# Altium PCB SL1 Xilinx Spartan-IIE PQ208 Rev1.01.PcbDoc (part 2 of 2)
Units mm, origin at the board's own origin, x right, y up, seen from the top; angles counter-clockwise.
Board outline 180.01 x 50.51 mm, 2 copper layers (Top Layer, Bottom Layer), stack 1.646 mm thick; 115 components, 126 nets, 642 pads, 225 vias.
Unrouted connection lines stored in the file: 2.
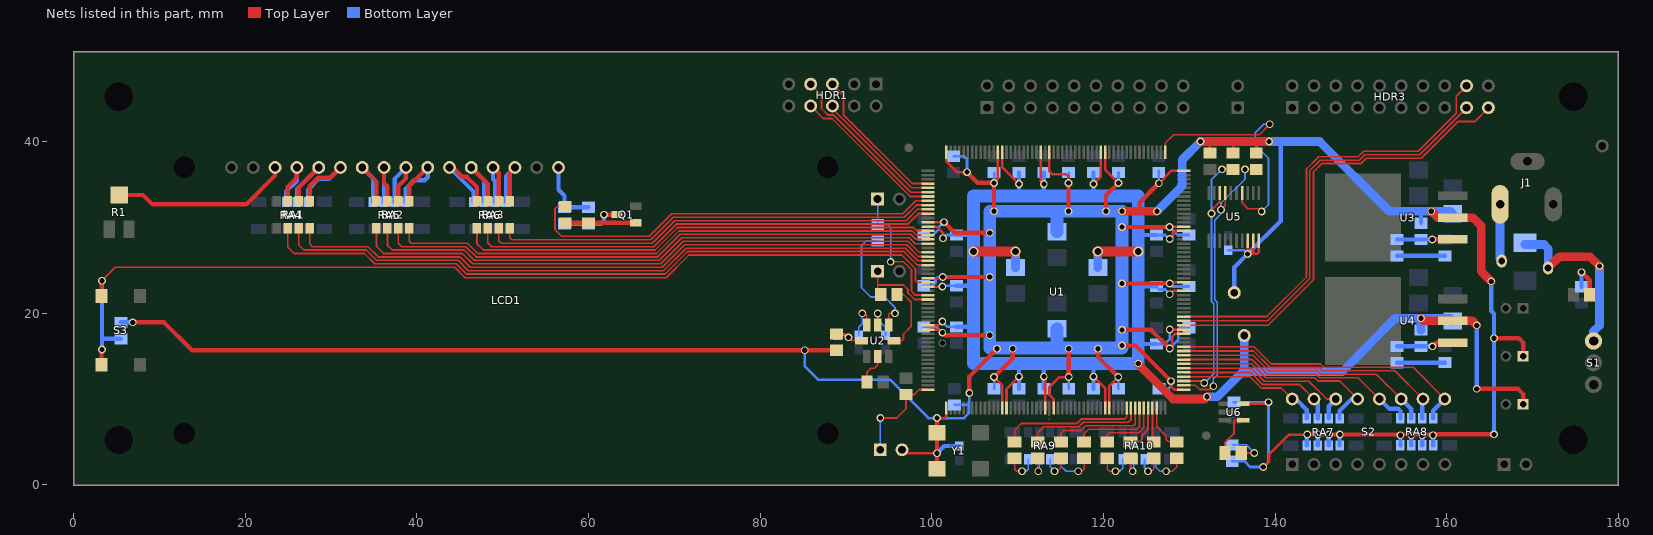
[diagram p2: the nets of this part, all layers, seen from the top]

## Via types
v1: diameter 0.9, hole 0.6, Top Layer to Bottom Layer, tented both sides, 168 vias
v2: diameter 1.5, hole 0.8, Top Layer to Bottom Layer, tented both sides, 27 vias
v3: diameter 1.2, hole 0.8, Top Layer to Bottom Layer, 18 vias
v4: diameter 1.2, hole 0.8, Top Layer to Bottom Layer, tented both sides, 11 vias
v5: diameter 0.9, hole 0.6, Top Layer to Bottom Layer, 1 vias

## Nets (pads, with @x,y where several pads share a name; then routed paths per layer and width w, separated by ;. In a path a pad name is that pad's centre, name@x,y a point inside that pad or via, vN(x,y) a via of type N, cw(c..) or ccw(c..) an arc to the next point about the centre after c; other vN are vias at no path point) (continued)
HB17: HDR3.17 U1.121 | length 50.6
  Top Layer w0.2: U1.121@129.35,19.125 139.109,19.125 144.05,24.066 144.05,36.646 145.254,37.85 149.823,37.85 150.448,38.475 156.835,38.475 HDR3.17@162.32,43.96
HB18: HDR3.18 U1.122 | length 52.6
  Top Layer w0.2: U1.122@129.35,19.625 139.044,19.625 143.65,24.231 143.65,36.812 145.088,38.25 149.657,38.25 150.307,38.9 156.694,38.9 161.1,43.306 161.1,45.28 HDR3.18@162.32,46.5
HB19: HDR3.19 U1.120 | length 53.4
  Top Layer w0.2: U1.120@129.35,18.625 139.175,18.625 144.475,23.925 144.475,36.505 145.42,37.45 149.988,37.45 150.613,38.075 157.025,38.075 161.291,42.341 163.241,42.341 HDR3.19@164.86,43.96
I\N\I\T\: R5.2 U1.107 U5.8 | length 32.6
  Top Layer w0.2: U1.107@129.35,12.125 131.5,12.125 v1(131.75,11.875) ; v1(132.575,31.625) 132.575,32.025 133.55,33 U5.8@133.55,34 ; v1(133.803,36.78) R5.2@135.1,36.775
  Bottom Layer w0.2: v1(131.75,11.875) 132.85,12.975 132.85,21.132 132.575,21.407 132.575,35.552 v1(133.803,36.78)
JTAG_NEXUS_TCK: HDR1.7 U1.6 | length 19.8
  Top Layer w0.2: HDR1.7@85.88,46.7 87.15,45.43 87.15,43.875 87.925,43.1 88.575,43.1 97.55,34.125 U1.6@99.55,34.125
JTAG_NEXUS_TDI: HDR1.5 U1.4 | length 17.3
  Top Layer w0.2: HDR1.5@88.42,46.7 89.7,45.42 89.7,43.15 97.725,35.125 U1.4@99.55,35.125
JTAG_NEXUS_TDO: HDR1.6 U1.5 | length 15.3
  Top Layer w0.2: HDR1.6@88.42,44.16 88.42,43.83 97.625,34.625 U1.5@99.55,34.625
JTAG_NEXUS_TMS: HDR1.8 U1.7 | length 18
  Top Layer w0.2: HDR1.8@85.88,44.16 87.34,42.7 88.375,42.7 97.45,33.625 U1.7@99.55,33.625
LCD_CONTRAST: LCD1.3 R1.W | length 21
  Top Layer w0.5: R1.W@5.3,33.8 8.1,33.8 9.2,32.7 20.113,32.7 23.48,36.067 LCD1.3@23.48,37
LCD_DB0: RA2.5 U1.20 | length 68.8
  Top Layer w0.2: RA2.5@35.295,29.925 35.295,27.8 36.12,26.975 45.3,26.975 46.5,25.775 68.41,25.775 71.035,28.4 97.225,28.4 98.5,27.125 U1.20@99.55,27.125
LCD_DB1: RA2.6 U1.18 | length 67.1
  Top Layer w0.2: RA2.6@36.565,29.925 36.565,27.935 37.125,27.375 45.5,27.375 46.7,26.175 68.244,26.175 70.869,28.8 97.391,28.8 98.066,28.125 U1.18@99.55,28.125
LCD_DB2: RA2.7 U1.17 | length 65.5
  Top Layer w0.2: RA2.7@37.835,29.925 37.835,28.165 38.225,27.775 45.7,27.775 46.9,26.575 68.078,26.575 70.703,29.2 97.556,29.2 98.131,28.625 U1.17@99.55,28.625
LCD_DB3: RA2.8 U1.16 | length 63.8
  Top Layer w0.2: RA2.8@39.105,29.925 39.105,28.395 39.325,28.175 45.9,28.175 47.1,26.975 67.913,26.975 70.538,29.6 97.722,29.6 98.197,29.125 U1.16@99.55,29.125
LCD_DB4: RA3.5 U1.15 | length 55.9
  Top Layer w0.2: RA3.5@46.995,29.925 46.995,28.105 47.725,27.375 67.747,27.375 70.372,30 97.888,30 98.263,29.625 U1.15@99.55,29.625
LCD_DB5: RA3.6 U1.11 | length 54.8
  Top Layer w0.2: RA3.6@48.265,29.925 48.265,28.235 48.725,27.775 67.581,27.775 70.206,30.4 97.197,30.4 98.422,31.625 U1.11@99.55,31.625
LCD_DB6: RA3.7 U1.10 | length 53.2
  Top Layer w0.2: RA3.7@49.535,29.925 49.535,28.465 49.825,28.175 67.416,28.175 70.041,30.8 97,30.8 98.325,32.125 U1.10@99.55,32.125
LCD_DB7: RA3.8 U1.9 | length 51.6
  Top Layer w0.2: RA3.8@50.805,29.925 50.805,28.82 51.05,28.575 67.25,28.575 69.875,31.2 96.8,31.2 98.225,32.625 U1.9@99.55,32.625
LCD_DB#0: LCD1.7 RA2.4 RA5.5 | length 9.2
  Top Layer w0.5: LCD1.7@33.64,37 35.295,35.345 RA2.4@35.295,33.075
  Bottom Layer w0.5: LCD1.7@33.64,37 34.895,35.745 RA5.5@34.895,32.975
LCD_DB#1: LCD1.8 RA2.3 RA5.6 | length 8.1
  Top Layer w0.5: LCD1.8@36.18,37 36.18,35.2 36.565,34.815 RA2.3@36.565,33.075
  Bottom Layer w0.5: RA5.6@36.165,32.975 36.165,36.985 LCD1.8@36.18,37
LCD_DB#2: LCD1.9 RA2.2 RA5.7 | length 8.8
  Top Layer w0.5: RA2.2@37.835,33.075 37.835,34.825 38.72,35.71 LCD1.9@38.72,37
  Bottom Layer w0.5: RA5.7@37.435,32.975 37.435,35.715 LCD1.9@38.72,37
LCD_DB#3: LCD1.10 RA2.1 RA5.8 | length 10.6
  Top Layer w0.5: RA2.1@39.105,33.075 39.105,34.845 LCD1.10@41.26,37
  Bottom Layer w0.5: RA5.8@38.705,32.975 38.705,34.505 39.7,35.5 40.9,35.5 41.26,35.86 LCD1.10@41.26,37
LCD_DB#4: LCD1.11 RA3.4 RA6.5 | length 11
  Top Layer w0.5: LCD1.11@43.8,37 44.2,37 45.297,35.903 45.797,35.903 46.995,34.705 RA3.4@46.995,33.075
  Bottom Layer w0.5: LCD1.11@43.8,37 46.595,34.205 RA6.5@46.595,32.975
LCD_DB#5: LCD1.12 RA3.3 RA6.6 | length 9.4
  Top Layer w0.5: LCD1.12@46.34,37 48.265,35.075 RA3.3@48.265,33.075
  Bottom Layer w0.5: LCD1.12@46.34,37 47.865,35.475 RA6.6@47.865,32.975
LCD_DB#6: LCD1.13 RA3.2 RA6.7 | length 8.3
  Top Layer w0.5: LCD1.13@48.88,37 49.535,36.345 RA3.2@49.535,33.075
  Bottom Layer w0.5: LCD1.13@48.88,37 48.88,35.655 49.135,35.4 RA6.7@49.135,32.975
LCD_DB#7: LCD1.14 RA3.1 RA6.8 | length 8.6
  Top Layer w0.5: RA3.1@50.805,33.075 50.805,36.385 LCD1.14@51.42,37
  Bottom Layer w0.5: RA6.8@50.405,32.975 50.405,35.985 LCD1.14@51.42,37
LCD_E: RA1.8 U1.21 | length 76.7
  Top Layer w0.2: RA1.8@27.505,29.925 27.505,28.095 27.825,27.775 34.3,27.775 35.5,26.575 45,26.575 46.2,25.375 68.575,25.375 71.2,28 97.059,28 98.434,26.625 U1.21@99.55,26.625
LCD_E#: LCD1.6 RA1.1 RA4.8 | length 12.5
  Top Layer w0.5: RA1.1@27.505,33.075 27.505,34.805 28.5,35.8 29.9,35.8 LCD1.6@31.1,37
  Bottom Layer w0.5: RA4.8@27.305,32.975 27.305,34.405 28.595,35.695 29.795,35.695 LCD1.6@31.1,37
LCD_LIGHT: R2.1 U1.8 | length 49.2
  Top Layer w0.2: R2.1@57.3,32.45 56.375,32.45 56.1,32.175 56.1,29.725 56.85,28.975 67.084,28.975 69.709,31.6 96.6,31.6 98.125,33.125 U1.8@99.55,33.125
LCD_RS: RA1.6 U1.23 | length 79.8
  Top Layer w0.2: RA1.6@24.965,29.925 24.965,27.735 25.725,26.975 33.9,26.975 35.1,25.775 44.6,25.775 45.8,24.575 68.907,24.575 71.532,27.2 96.725,27.2 98.3,25.625 U1.23@99.55,25.625
LCD_RS#: LCD1.4 RA1.3 RA4.6 | length 8.9
  Top Layer w0.5: RA1.3@24.965,33.075 24.965,34.79 26.02,35.845 LCD1.4@26.02,37
  Bottom Layer w0.5: RA4.6@24.765,32.975 24.765,34.195 26.02,35.45 LCD1.4@26.02,37
LCD_RW: RA1.7 U1.22 | length 78.2
  Top Layer w0.2: RA1.7@26.235,29.925 26.235,27.965 26.825,27.375 34.1,27.375 35.3,26.175 44.8,26.175 46,24.975 68.741,24.975 71.366,27.6 96.894,27.6 98.369,26.125 U1.22@99.55,26.125
LCD_RW#: LCD1.5 RA1.2 RA4.7 | length 10
  Top Layer w0.5: RA1.2@26.235,33.075 26.235,34.675 LCD1.5@28.56,37
  Bottom Layer w0.5: RA4.7@26.035,32.975 26.035,34.475 LCD1.5@28.56,37
LEDS0: LED0.1 U1.102 | length 5.5
  Top Layer w0.2: U1.102@126.2,8.975 126.2,6.825 127.325,5.7 127.325,5.275 127.575,5.025 LED0.1@128.55,5.025
LEDS1: LED1.1 U1.101 | length 4
  Top Layer w0.2: U1.101@125.7,8.975 125.7,8.875 125.7,5.175 LED1.1@125.85,5.025
LEDS2: LED2.1 U1.100 | length 5.4
  Top Layer w0.2: LED2.1@123.15,5.025 124.175,5.025 124.5,5.35 124.5,5.775 125.2,6.475 U1.100@125.2,8.975
LEDS3: LED3.1 U1.99 | length 7.7
  Top Layer w0.2: LED3.1@120.45,5.025 120.45,5.875 120.675,6.1 124.1,6.1 124.7,6.7 U1.99@124.7,8.975
LEDS4: LED4.1 U1.98 | length 9.9
  Top Layer w0.2: LED4.1@117.75,5.025 117.75,6 118.25,6.5 123.9,6.5 124.2,6.8 U1.98@124.2,8.975
LEDS5: LED5.1 U1.97 | length 12
  Top Layer w0.2: LED5.1@115.05,5.025 115.05,6.05 115.35,6.35 117.35,6.35 117.9,6.9 123.525,6.9 123.7,7.075 U1.97@123.7,8.975
LEDS6: LED6.1 U1.96 | length 13.9
  Top Layer w0.2: LED6.1@112.35,5.025 112.35,6.075 113.05,6.775 117.125,6.775 117.65,7.3 122.9,7.3 123.2,7.6 U1.96@123.2,8.975
LEDS7: LED7.1 U1.95 | length 16.1
  Top Layer w0.2: LED7.1@109.65,5.025 109.65,6.375 110.45,7.175 116.959,7.175 117.484,7.7 122.475,7.7 122.7,7.925 U1.95@122.7,8.975
M0: JP5.1 R7.2 U1.52 | length 11.6
  Top Layer w0.2: v1(94,7.8) 95.9,7.8 96.989,8.889 96.989,10.555 97.98,10.555 98.55,11.125 U1.52@99.55,11.125
  Bottom Layer w0.2: JP5.1@94,4.1 v1(94,7.8)
NetC15_1: C15.1 R11.2 U2.8 | length 4.6
  Top Layer w0.2: R11.2@88.88,17.6 89.9,17.6 90.7,16.8 U2.8@91.8,16.8
  Bottom Layer w0.2: C15.1@89,17.45 89.78,17.45 v1(90.3,17.2)
NetC16_1: C16.1 U2.6 | length 4.2
  Top Layer w0.2: U2.6@93.697,18.663 93.702,18.668 v1(93.702,19.988)
  Bottom Layer w0.2: v1(93.702,19.988) 93.702,19.28 94.6,18.383 C16.1@94.6,17.45
NetC19_1: C19.1 U2.7 | length 4.5
  Top Layer w0.2: v1(91.9,20) 92.2,20 92.43,19.77 U2.7@92.43,18.65
  Bottom Layer w0.2: C19.1@91.5,17.45 91.5,18.392 91.9,18.792 v1(91.9,20)
NetD1_2: D1.2 F1.2 S1.3 | length 21.2
  Top Layer w1: F1.2@171.8,25.3 173.1,26.6 176.7,26.6 v1(177.8,25.5)
  Bottom Layer w1: D1.2@169.1,28.022 171.325,28.025 171.8,27.55 F1.2@171.8,25.3 ; S1.3@177.1,16.78 177.1,17.9 177.8,18.58 v1(177.8,25.5)
NetLCD1_16: LCD1.16 R8.1 R9.1 | length 7.7
  Bottom Layer w0.5: LCD1.16@56.5,37 56.5,34.4 57.2,33.7 57.2,32.35 R9.1@60,32.35
NetLED0_2: LED0.2 RA10.5 | length 5.5
  Top Layer w0.2: v1(127.3,1.6) 128.05,1.6 128.55,2.1 LED0.2@128.55,3.125
  Bottom Layer w0.2: RA10.5@126.055,3 126.055,2.125 126.58,1.6 ; 126.58,1.6 v1(127.3,1.6) 126.58,1.6
NetLED1_2: LED1.2 RA10.6 | length 3.6
  Top Layer w0.2: v1(125.2,1.6) 125.6,1.6 125.85,1.85 LED1.2@125.85,3.125
  Bottom Layer w0.2: RA10.6@124.785,3 124.785,2.015 v1(125.2,1.6)
NetLED2_2: LED2.2 RA10.7 | length 3.1
  Top Layer w0.2: LED2.2@123.15,3.125 123.15,1.85 v1(123.4,1.6)
  Bottom Layer w0.2: v1(123.4,1.6) 123.515,1.715 RA10.7@123.515,3
NetLED3_2: LED3.2 RA10.8 | length 4.4
  Top Layer w0.2: LED3.2@120.45,3.125 120.45,1.85 120.7,1.6 v1(121.4,1.6)
  Bottom Layer w0.2: v1(121.4,1.6) 121.9,1.6 122.245,1.945 RA10.8@122.245,3
NetLED4_2: LED4.2 RA9.5 | length 5.1
  Top Layer w0.2: v1(117.055,1.6) 117.45,1.6 117.75,1.9 LED4.2@117.75,3.125
  Bottom Layer w0.2: RA9.5@115.055,3 115.055,2.2 115.655,1.6 v1(117.055,1.6)
NetLED5_2: LED5.2 RA9.6 | length 3.6
  Top Layer w0.2: v1(114.3,1.6) 114.6,1.6 115.05,2.05 LED5.2@115.05,3.125
  Bottom Layer w0.2: RA9.6@113.785,3 113.785,2.115 v1(114.3,1.6)
NetLED6_2: LED6.2 RA9.7 | length 3
  Top Layer w0.2: LED6.2@112.35,3.125 112.35,1.65 v1(112.4,1.6)
  Bottom Layer w0.2: v1(112.4,1.6) 112.515,1.715 RA9.7@112.515,3
NetLED7_2: LED7.2 RA9.8 | length 4.2
  Top Layer w0.2: LED7.2@109.65,3.125 109.65,1.85 109.9,1.6 v1(110.5,1.6)
  Bottom Layer w0.2: v1(110.5,1.6) 111,1.6 111.245,1.845 RA9.8@111.245,3
NetLED8_1: LED8.1 R20.1 | length 4.5
  Top Layer w0.2: LED8.1@136.05,3.725 v1(137.575,3.725)
  Bottom Layer w0.2: R20.1@135,4.675 136.625,4.675 v1(137.575,3.725)
NetLED8_2: LED8.2 U6.4 | length 5.2
  Top Layer w0.2: LED8.2@134.15,3.725 134.15,4.925 135.2,5.975 135.2,7.4 135.35,7.55 U6.4@136.275,7.55
NetLED9_1: LED9.1 R15.1 | length 4.7
  Top Layer w0.5: v1(175.7,24.8) 176.65,23.85 LED9.1@176.65,22.15
  Bottom Layer w0.5: R15.1@175.7,23.1 v1(175.7,24.8)
NetQ1_1: Q1.1 R2.2 R3.2 | length 8.2
  Top Layer w0.5: R2.2@57.3,30.55 Q1.1@65.5,30.55
NetQ1_3: Q1.3 R8.2 R9.2 | length 6.9
  Top Layer w0.5: v1(61.8,31.5) Q1.3@63.3,31.5
  Bottom Layer w0.5: R8.2@57.2,30.45 61.45,30.45 61.8,30.8 v1(61.8,31.5)
NetR10_2: R10.2 U2.2 | length 3.7
  Top Layer w0.2: R10.2@92.45,12 92.45,13.15 92.9,13.6 93.28,13.6 93.7,14.02 U2.2@93.7,14.95
NetR12_1: R12.1 R13.2 U3.1 | length 6.5
  Top Layer w0.5: v1@158.32,28.62 U3.1@160.7,28.62
  Bottom Layer w0.5: R12.1@154.2,28.6 157,28.6 v1(158.3,28.6)
NetR12_2: R12.2 R14.2 | length 5.6
  Bottom Layer w0.5: R12.2@154.2,26.7 R14.2@159.8,26.7
NetR17_1: R17.1 R18.2 U4.1 | length 6.7
  Top Layer w0.5: v1(158.35,16.15) 158.8,16.6 U4.1@160.7,16.6
  Bottom Layer w0.5: R17.1@154.2,16.15 v1(158.35,16.15)
NetR17_2: R17.2 R19.1 | length 5.6
  Bottom Layer w0.5: R17.2@154.2,14.25 R19.1@159.8,14.25
PROG_B: R6.2 U1.106 U5.7 | length 34.3
  Top Layer w0.2: U1.106@129.35,11.625 130.725,11.625 131.225,11.125 132.425,11.125 v1(132.8,11.5) ; v1(133.7,32.075) 134.2,32.575 U5.7@134.2,34 ; v1(136.5,36.775) R6.2@137.8,36.775
  Bottom Layer w0.2: v1(132.8,11.5) 132.8,12.359 133.25,12.809 133.25,21.297 132.975,21.572 132.975,30.867 133.7,31.592 133.7,32.85 136.5,35.65 v1(136.5,36.775)
PWR_IN: F1.1 J1.1 | length 7.9
  Bottom Layer w1: J1.1@166.2,33.95 166.2,26.35 F1.1@166.4,26.1
SW0: RA7.1 S2.16 U1.108 | length 17.8
  Top Layer w0.2: U1.108@129.35,12.625 137.075,12.625 138.4,11.3 140.72,11.3 S2.16@141.999,10.021
  Bottom Layer w0.5: S2.16@142,10.02 142.43,10.02 143.695,8.755 143.695,7.755 143.7,7.75 143.7,8.63
SW1: RA7.2 S2.15 U1.109 | length 20.6
  Top Layer w0.2: U1.109@129.362,13.113 137.153,13.113 138.566,11.7 142.85,11.7 S2.15@144.53,10.02
  Bottom Layer w0.5: S2.15@144.54,10.02 S2.15@144.965,9.595 ; RA7.2@144.965,7.875 S2.15@144.965,9.595 ; RA7.2@144.97,7.75 144.97,9.59 S2.15@144.965,9.595
SW2: RA7.3 S2.14 U1.110 | length 21.8
  Top Layer w0.2: U1.110@129.362,13.613 137.218,13.613 138.731,12.1 143.935,12.1 146.014,10.021 S2.14@147.079,10.021
  Bottom Layer w0.5: RA7.3@146.24,7.75 146.24,9.18 S2.14@147.08,10.02
SW3: RA7.4 S2.13 U1.111 | length 25.5
  Top Layer w0.2: U1.111@129.362,14.113 137.284,14.113 138.897,12.5 144.614,12.5 145.004,12.109 147.521,12.109 S2.13@149.61,10.02
  Bottom Layer w0.5: RA7.4@147.51,7.75 147.51,8.635 148.895,10.02 S2.13@149.62,10.02
SW4: RA8.1 S2.12 U1.112 | length 28.6
  Top Layer w0.2: U1.112@129.362,14.613 137.35,14.613 139.063,12.9 144.779,12.9 145.17,12.509 149.661,12.509 S2.12@152.15,10.02
  Bottom Layer w0.5: S2.12@152.16,10.02 153.309,8.871 154.346,8.871 154.6,8.617 RA8.1@154.6,7.75
SW5: RA8.2 S2.11 U1.113 | length 30.2
  Top Layer w0.2: U1.113@129.362,15.113 137.415,15.113 139.228,13.3 144.945,13.3 145.336,12.909 151.801,12.909 S2.11@154.69,10.02
  Bottom Layer w0.5: S2.11@154.7,10.02 155.87,8.85 RA8.2@155.87,7.75
SW6: RA8.3 S2.10 U1.114 | length 32.5
  Top Layer w0.2: U1.114@129.362,15.613 137.481,15.613 139.394,13.7 145.111,13.7 145.501,13.309 153.941,13.309 S2.10@157.23,10.02
  Bottom Layer w0.5: RA8.3@157.14,7.75 157.14,9.92 S2.10@157.24,10.02
SW7: RA8.4 S2.9 U1.115 | length 35.8
  Top Layer w0.2: U1.115@129.362,16.113 137.547,16.113 139.56,14.1 145.277,14.1 145.667,13.709 156.081,13.709 S2.9@159.77,10.02
  Bottom Layer w0.5: RA8.4@158.41,7.75 158.41,8.65 S2.9@159.78,10.02
TDI_C: U1.157 U5.4 | length 30.2
  Top Layer w0.2: U1.157@127.2,38.775 127.2,39.85 128.175,40.825 138.175,40.825 v1(139.375,42.025) ; U5.4@136.15,34 136.15,32.875 136.825,32.2 138.107,32.2 v1(138.43,31.877)
  Bottom Layer w0.2: v1(138.43,31.877) 139.225,32.672 139.225,38.065 137.7,39.59 137.7,41.05 138.675,42.025 v1(139.375,42.025)
TEST: R16.2 S3.1 S3.2 U1.27 | length 114.4
  Top Layer w0.2: v1(3.3,23.8) 4.865,25.365 44.4,25.365 45.615,24.15 69.05,24.15 71.7,26.8 96.5,26.8 98.1,25.2 98.1,23.825 98.3,23.625 U1.27@99.55,23.625
  Top Layer w0.5: S3.1@3.25,13.99 3.25,15.75 v1(3.3,15.8) ; S3.2@3.25,22 v1@3.25,23.75
  Bottom Layer w0.5: v1(3.3,15.8) v1(3.3,23.8) ; 3.3,17.05 R16.2@5.5,17.05
VCCINT: C3.1 C7.1 C8.1 C10.1 C20.1 C21.1 C25.1 C26.1 C28.1 C29.1 C30.1 C32.1 C34.2 C38.1 C39.1 C41.1 R18.1 TP3.1 U1.14 U1.28 U1.37 U1.67 U1.76 U1.90 U1.119 U1.128 U1.142 U1.172 U1.186 U1.195 U4.2 | length 236.6
  Top Layer w0.3: U1.37@99.548,18.613 100.788,18.613 v1(101.225,19.05) ; U1.28@99.548,23.113 v1@101.225,23.113 ; U1.14@99.548,30.113 100.537,30.113 101.3,29.35 v1(101.3,28.75) ; U1.195@108.198,38.763 108.198,37.027 v1(110.15,35.075) ; U1.67@108.698,8.963 108.698,11.173 v1(110.15,12.625) ; U1.186@112.698,38.763 112.698,35.427 v1(113.05,35.075) ; v1(113.05,12.625) 113.198,12.477 U1.76@113.198,8.963 ; v1(118.85,12.625) 120.198,11.277 U1.90@120.198,8.963 ; v1(118.85,35.075) 119.698,35.923 U1.172@119.698,38.763 ; v1@127.725,18.113 U1.119@129.348,18.113 ; v1(127.725,22.225) 128.113,22.613 U1.128@129.348,22.613 ; v1(127.725,28.65) 128.1,29.025 128.1,29.318 128.395,29.613 U1.142@129.348,29.613
  Top Layer w0.5: v1(163.5,11.2) 168.3,11.2 168.9,10.6 C3.1@168.9,9.4
  Top Layer w1: v1(124.05,14.175) 124.15,13.975 128.106,10.019 131.819,10.019 v1(132.075,10.275) ; v1(157,19.425) 157.285,19.14 162.96,19.14 v1(163.5,18.6)
  Top Layer w1.2: v4(104.85,27.2) v4(109.75,27.2) ; v4(119.35,27.2) v4(124.05,27.2)
  Bottom Layer w0.3: v1(101.225,19.05) 101.85,18.425 C32.1@102.85,18.425 ; v1(101.225,23.125) 101.225,23.225 C25.1@102.85,23.225 ; v1(101.3,28.75) 101.675,29.125 C20.1@102.85,29.125 ; C34.2@126.15,16.425 127.121,16.425 ; C26.1@126.15,23.125 126.5,22.775 127.175,22.775 v1(127.725,22.225) ; C21.1@126.15,29.125 127.175,29.125 127.65,28.65 v1(127.725,28.65) ; 127.111,16.436 127.21,16.535 ; 127.222,16.522 127.725,17.025 v1(127.725,18.125)
  Bottom Layer w0.5: C32.1@102.85,18.425 104.85,18.425 ; C25.1@102.85,23.225 104.85,23.225 ; C20.1@102.85,29.125 104.85,29.125 ; C38.1@110.15,11.225 v1(110.15,12.625) 110.15,13.975 ; 110.15,33.8 v1(110.15,35.075) C7.1@110.15,36.4 ; C39.1@113.05,11.225 113.05,13.975 ; 113.05,33.8 C8.1@113.05,36.4 ; C41.1@118.85,11.225 118.85,13.975 ; 118.85,33.8 C10.1@118.85,36.4 ; 124.05,16.425 C34.2@126.15,16.425 ; 124.05,23.125 C26.1@126.15,23.125 ; 124.05,29.125 C21.1@126.15,29.125 ; v1(163.5,11.2) v1(163.5,18.6)
  Bottom Layer w1: C28.1@109.75,25.325 v4(109.75,27.2) ; C29.1@119.35,25.325 v4(119.35,27.2) ; v1(132.075,10.275) 133.275,10.275 136.175,13.175 147.8,13.175 153.975,19.425 160.375,19.425 C30.1@160.7,19.1 ; 136.4,13.175 TP3.1@136.4,17.4 ; R18.1@157,18.05 v1(157,19.425)
  Bottom Layer w1.5: 104.85,14.175 v1(124.05,14.175) 124.05,33.675 118.85,33.675 104.85,33.675 v4(104.85,27.2) 104.85,14.175
VCCO: C2.1 C4.1 C5.2 C6.1 C9.1 C11.1 C12.1 C14.1 C17.2 C18.2 C22.2 C23.1 C24.2 C31.1 C33.1 C35.1 C36.2 C37.1 C40.1 C42.1 C43.1 C44.2 C45.1 JP5.2 R4.1 R5.1 R6.1 R11.1 R13.1 R16.1 R20.2 RA7.5 RA7.6 RA7.7 RA7.8 RA8.5 RA8.6 RA8.7 RA8.8 TP2.1 U1.13 U1.26 U1.38 U1.53 U1.66 U1.78 U1.91 U1.105 U1.118 U1.130 U1.143 U1.156 U1.171 U1.184 U1.196 U1.208 U3.2 U5.18 U5.19 U5.20 U6.5 Y1.1 Y1.4 | length 536.7
  Top Layer w0.3: JP5.2@96.54,4.1 96.94,3.7 v1(100.6,3.7) ; U1.38@99.548,18.113 100.862,18.113 v1@101.525,17.45 ; U1.26@99.548,24.113 101.163,24.113 v1(101.275,24.225) v1@101.4,24.225 ; U1.13@99.548,30.613 v1@101.425,30.613 ; v1(100.6,7.8) 101.5,7.8 101.698,7.998 U1.53@101.698,8.963 ; U1.208@101.698,38.763 101.698,37.677 102.925,36.45 v1(104.1,36.45) ; v1(107.25,12.575) 108.198,11.627 U1.66@108.198,8.963 ; v1(107.25,35.2) 107.698,35.648 U1.196@107.698,38.763 ; U1.184@113.698,38.763 113.698,36.552 114.025,36.225 115.65,36.225 115.925,35.95 v1(115.925,35.2) ; U1.78@114.198,8.963 114.198,10.002 113.7,10.5 113.7,11.4 114.875,12.575 v1(115.95,12.575) ; U1.171@120.198,38.763 120.198,36.752 v1(121.75,35.2) ; U1.91@120.698,8.963 120.698,11.548 v1(121.725,12.575) ; v1(126.45,35.15) 127.925,36.625 U1.156@129.35,36.625 ; v1(127.7,30.05) 127.7,30.113 U1.143@129.348,30.113 ; v1(127.725,15.9) 128.017,16.192 128.017,17.273 128.357,17.613 U1.118@129.348,17.613 ; v1(127.725,23.475) v1@127.875,23.625 ; v1(127.875,12.1) 127.875,11.5 128.262,11.113 U1.105@129.348,11.113 ; v1@127.887,23.613 U1.130@129.348,23.613 ; R4.1@132.4,38.675 132.4,39.85 ; R5.1@135.1,38.675 135.1,39.85 ; U6.5@136.275,9.45 139.025,9.45 v1(139.225,9.65) ; U5.18@136.8,28.45 v1(136.8,26.925) 137.9,26.925 138.1,27.125 U5.20@138.1,28.45 ; 137.45,26.925 U5.19@137.45,28.45 ; R6.1@137.8,38.675 137.8,40.075 137.825,40.1 ; v1(138.625,2.1) 139.298,2.773 139.298,3.558 141.615,5.875 v1(143.735,5.875)
  Top Layer w0.5: v1(6.9,18.95) 10.55,18.95 13.8,15.7 v1(85.2,15.7) R11.1@88.88,15.7 ; Y1.1@100.6,1.6 v1(100.6,7.8) ; v1(101.275,24.225) v1(106.75,24.225) ; v1(101.425,30.625) 102.675,29.375 v1(106.75,29.375) ; v1@101.525,17.45 v1(106.75,17.45) ; v1(104.1,36.45) 105.35,35.2 v1(107.25,35.2) v1(107.25,31.9) ; v1(104.375,10.725) 104.375,12.65 v1(107.6,15.875) ; v1(107.25,12.575) 109.425,14.75 v1(109.425,15.875) ; v1(115.925,31.9) v1(115.925,35.2) ; v1(115.95,12.575) v1(115.95,15.875) ; v1(119.375,15.875) 119.375,14.925 v1(121.725,12.575) ; v1(120.3,31.9) 120.3,33.75 v1(121.75,35.2) ; v1(122.15,16.25) 123.725,16.25 v1(127.875,12.1) ; v1(122.15,18.075) 125.55,18.075 v1(127.725,15.9) ; v1(122.15,23.475) v1(127.725,23.475) ; v1(122.15,30.05) v1(127.7,30.05) ; 124.225,31.9 124.225,32.925 v1(126.45,35.15) ; v1(131.3,40.025) 131.55,39.85 137.55,39.85 ; v1(143.735,5.875) v1@158.445,5.875 ; v1(158.4,5.8) 158.5,5.9 v1(165.5,5.9) ; v1(165.5,17.1) 168.4,17.1 168.9,16.6 C2.1@168.9,15
  Top Layer w1: v1(122.15,31.9) v1(126.225,31.9) ; v1(131.3,40.025) v1(139.3,40.025) ; v1(158.2,31.9) 158.94,31.16 163.04,31.16 164,30.2 164,24.9 v1(165.175,23.725)
  Bottom Layer w0.3: v1(85.2,15.7) 85.2,13.825 86.75,12.275 95.15,12.275 99.6,7.8 103.75,7.8 104.375,8.425 v1(104.375,10.725) ; C31.1@99.05,18.425 100.55,18.425 v1(101.225,17.75) ; C22.2@99.05,23.225 100.075,23.225 100.425,23.575 100.425,23.975 100.675,24.225 v1(101.275,24.225) ; C17.2@99.05,29.125 100.125,29.125 100.725,29.725 100.725,29.925 v1(101.425,30.625) ; C5.2@102.55,38.3 103.775,38.3 104.1,37.975 v1(104.1,36.45) ; C36.2@102.65,9.325 104.375,9.325 ; C37.1@107.25,11.225 v1(107.25,12.575) ; v1(107.25,35.2) C6.1@107.25,36.4 ; v1(115.925,35.2) C9.1@115.95,36.4 ; C40.1@115.95,11.225 v1(115.95,12.575) ; v1(121.725,12.575) 121.725,11.25 C42.1@121.75,11.225 ; v1(121.75,35.2) C11.1@121.75,36.4 ; C43.1@126.45,11.225 127.575,11.225 127.875,11.525 v1(127.875,12.1) ; v1(126.45,35.15) C12.1@126.45,36.625 ; v1(127.7,30.05) 128.625,29.125 C18.2@129.95,29.125 ; v1(127.725,15.9) 128.7,16.875 128.7,18.125 128.9,18.325 C35.1@129.95,18.325 ; v1(127.725,23.475) 128.075,23.125 C24.2@129.95,23.125 ; C4.1@134.525,27.35 136.375,27.35 v1(136.8,26.925) ; R20.2@135,2.775 136.425,2.775 137.1,2.1 v1(138.625,2.1) 139.225,2.7 v1(139.225,9.65) C44.2@135.2,9.65
  Bottom Layer w0.5: R16.1@5.5,18.95 v1(6.9,18.95) ; v1(100.6,3.7) 101.45,4.55 C45.1@103.2,4.55 ; TP2.1@135.233,22.4 135.233,25.358 v1(136.8,26.925) 140.65,30.75 140.65,40.025 v1(139.3,40.025) ; RA7.8@143.7,4.6 v1@143.7,5.84 ; RA7.7@144.97,4.6 v1@144.97,5.84 ; RA7.6@146.24,4.6 v1@146.24,5.84 ; RA7.5@147.51,4.6 v1@147.51,5.84 ; RA8.8@154.6,4.6 v1@154.6,5.84 ; RA8.7@155.87,4.6 v1@155.87,5.84 ; R13.1@157,30.55 157,31.925 ; RA8.6@157.14,4.6 v1@157.14,5.84 ; RA8.5@158.41,4.6 v1@158.41,5.84 ; v1(165.175,23.725) 165.175,20.275 165.5,19.95 v1(165.5,17.1) v1(165.5,5.9)
  Bottom Layer w1: v1(126.225,31.9) 129.175,34.85 129.175,37.9 v1(131.3,40.025) ; v1(139.3,40.025) 145.175,40.025 153.3,31.9 160.4,31.9 C14.1@160.7,31.6
  Bottom Layer w1.5: 114.6,16 C33.1@114.6,18.2 ; C23.1@114.6,29.5 114.6,31.9 ; 114.6,31.9 v1(122.15,31.9) 122.15,15.975 106.75,15.975 v1(106.75,17.45) v1(106.75,24.225) 106.75,31.9 v1(107.25,31.9) 114.6,31.9
  other v1: 154.59,5.8 155.86,5.8 157.13,5.8 145.005,5.875 146.275,5.875 147.545,5.875
XOUT: R22.2 U2.5 | length 15
  Top Layer w0.2: U2.5@94.97,18.65 94.97,19.57 94.97,19.87 95.1,20 v1(95.7,20)
  Bottom Layer w0.2: R22.2@93.711,28.455 92.355,28.455 91.8,27.8 91.8,23 92.9,21.9 94.514,21.9 95.7,20.714 v1(95.7,20) v1@95.4,20.3
XOUT_ALT: JP3.1 R22.1 U1.30 | length 16
  Top Layer w0.2: v1(95.2,26) 96.7,26 97.633,25.067 97.633,22.567 98.075,22.125 U1.30@99.55,22.125
  Bottom Layer w0.2: JP3.1@93.693,33.31 93.693,30.373 93.711,30.355 94.845,30.355 95.2,30 v1(95.2,26)
YOUT: R21.2 U2.4 | length 7.9
  Top Layer w0.2: U2.4@95.6,16.8 96.5,16.8 96.7,17 96.7,17.6 97.6,18.5 97.6,21.286 96.697,22.189 R21.2@95.945,22.189
YOUT_ALT: JP4.1 R21.1 U1.31 | length 9.6
  Top Layer w0.2: JP4.1@93.693,24.91 93.693,22.54 R21.1@94.045,22.189 ; 93.793,23.3 96.7,23.3 97.233,22.767 97.233,22.367 97.975,21.625 U1.31@99.55,21.625
pads on no net: HDR2.1 HDR3.1 LCD1.M1 LCD1.M2 LCD1.M3 LCD1.M4 RA1.4 RA1.5 RA4.5 RA4.STP RA5.STP RA6.STP RA7.STP RA8.STP RA9.STP RA10.STP U1.3 U1.24 U1.29 U1.33 U1.34 U1.35 U1.36 U1.40 U1.41 U1.42 U1.43 U1.44 U1.45 U1.46 U1.47 U1.48 U1.49 U1.55 U1.56 U1.57 U1.58 U1.59 U1.60 U1.61 U1.62 U1.63 U1.64 U1.68 U1.69 U1.70 U1.71 U1.73 U1.74 U1.75 U1.81 U1.82 U1.83 U1.84 U1.86 U1.87 U1.88 U1.89 U1.93 U1.94 U1.116 U1.139 U1.140 U1.141 U1.145 U1.146 U1.147 U1.148 U1.149 U1.150 U1.151 U1.152 U1.154 U1.192 U1.193 U1.194 U1.198 U1.199 U1.200 U1.201 U1.202 U1.203 U1.204 U1.205 U1.206 U1.FID1 U1.FID2 U2.0 U2.1 U3.4 U4.4 U5.2 U5.9 U5.12 U5.13 U5.14 U5.15 U5.16 U6.1

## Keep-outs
Keep-Out Layer:
  circle w0.2: c174.75,45.25 r4
  circle w0.2: c5.25,45.25 r4
  circle w0.2: c174.75,5.275 r4
  circle w0.2: c5.25,5.25 r4
  lines w0.635: 0,0 180,0 180,50.5 0,50.5 0,0

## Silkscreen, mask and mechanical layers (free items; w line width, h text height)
Top Overlay:
  drawing of 3334 lines, arcs and shapes, not listed
  text "Altium Advanced Training: '.Pcb_File_Name_No_Path'" at 0.954,54.062 h1.52
  text "SL" at 54.182,46.321 h1.3
  text "REV 1.01" at 59.262,46.321 h1.3
  text "CONTRAST" at 1.9,26.6 h1
  text "PWR" at 179.324,20.574 h1.2 r90
  text "TEST/" at 3.6,11.5 h1
  text "RESET" at 3.4,9.8 h1
  text "7" at 109.6,6.5 h1.2
  text "6" at 112,6.5 h1.2
  text "5" at 114.7,6.5 h1.2
  text "4" at 117.3,6.5 h1.2
  text "3" at 120.1,6.5 h1.2
  text "2" at 122.7,6.5 h1.2
  text "1" at 125.5,6.5 h1.2
  text "0" at 128.1,6.5 h1.2
  text "DONE" at 132.968,0.946 h1.2
Unit PCB Boundary:
  lines w0.2: 0,0 0,50.5 180,50.5 180,0 0,0
  text "PCB boundary coincides with centre-line of tracks" at 0,-10 h0.75
Overlay boundary:
  lines w0.2: 0.508,0.508 179.492,0.508 179.5,50.025 0.508,50.038 0.508,0.508
  text "PCB boundary coincides with centre-line of tracks" at 0,-10 h0.75
LayerID:
  text ".Printout_Name" at 0,-6 h0.75
Dimensions:
  text "Dimensions in millimetres (mm)" at 0,-8 h0.75
Design Information:
  drawing of 719 lines, arcs and shapes, not listed
  text "Spirit Level Rev 1.01" at 282.247,157.974 h1.27
  text "DESIGN INFORMATION" at 226.24,157.847 h1.52
  text "BOARD NAME:" at 263.832,157.847 h1.52
  text "BOARD TECHNOLOGY" at 226.24,155.307 h1.52
  text "BOARD SIZE (REFER ALSO PROFILING INFORMATION)" at 274.5,155.307 h1.27
  text "50.50mm" at 282.22,153.033 h1.52
  text "15.000" at 242.039,152.945 h1.52
  text "180.00mm" at 305.22,152.933 h1.52
  text "7.874" at 256.009,152.818 h1.52
  text "7.874" at 229.066,152.767 h1.52
  text "(Unit)" at 321.29,152.709 h1.52
  text "X" at 298.169,152.259 h1.78
  text "(MIN. TRACK/   PADS  /CLEARANCE IN 0.001'')" at 224.716,150.227 h1.27
  text "MINIMUM ANNULAR RING 0.05MM (0.002'') EXTERNAL PER IPC-2221 CLASS 3 LEVEL C AND IS THE" at 226.24,147.687 h1.27
  text "MANUFACTURING REGISTRATION ALLOWANCE" at 226.24,145.401 h1.27
  text "LAND SIZE CALCULATION MINIMUM - NOMINAL HOLE SIZE + 0.508MM (0.020'')" at 226.24,142.607 h1.27
  text "AS INSTRUCTED" at 312.27,138.213 h1.52
  text "X" at 263.883,138.086 h1.52
  text "CIRCUIT TYPE:" at 226.24,138.035 h1.52
  text "SS" at 249.1,138.035 h1.27
  text "DS" at 266.88,138.035 h1.27
  text "X" at 281.485,138.035 h1.52
  text "PTH" at 284.66,138.035 h1.27
  text "ML" at 295.582,138.035 h1.27
  text "X" at 299.392,138.035 h1.52
  text "No. OFF" at 302.44,138.035 h1.27
  text "FINGER CONNECTOR DIM PER:" at 226.24,134.987 h1.52
  text "AS SHOWN" at 302.44,134.987 h1.27
  text "No. OFF TOTAL" at 243.004,132.193 h1.52
  text "ONE SIDE" at 284.66,132.193 h1.27
  text "BOTH SIDES" at 302.44,131.939 h1.27
  text "VIAS:" at 226.24,129.272 h1.52
  text "NONE" at 237.67,129.272 h1.14
  text "X" at 246.052,129.272 h1.52
  text "FEED THRU'" at 249.1,129.272 h1.14
  text "X" at 263.832,129.272 h1.52
  text "TENTED" at 266.88,129.272 h1.14
  text "BURIED LAYER SEQUENCE" at 284.66,129.272 h1.14
  text "UNIQUE DRILL" at 249.1,126.224 h1.14
  text "2 SIZE" at 266.88,126.224 h1.14
  text "BLIND LAYER SEQUENCE" at 284.66,126.224 h1.14
  text "Layer Stack Manager (Protel)" at 261.673,123.938 h1.27
  text "X" at 299.392,123.938 h1.52
  text "AS SHOWN" at 302.44,123.938 h1.27
  text "LAYER CONSTRUCTION PER:" at 226.24,123.811 h1.52
  text "Protel" at 307.266,121.271 h1.27
  text "(PFW)" at 317.553,121.144 h1.27
  text "ARTWORK:" at 226.24,121.017 h1.52
  text "MANUAL" at 249.1,121.017 h1.27
  text "DIGITISED" at 266.88,121.017 h1.27
  text "X" at 281.612,121.017 h1.52
  text "CAD" at 284.66,121.017 h1.27
  text "TYPE" at 295.582,121.017 h1.27
  text "ARTWORK/PATTERN MASTER LIST" at 226.24,116.318 h1.52
  text "DESCRIPTION" at 227.51,113.905 h1.27
  text "DRAWING No./CAD FILE REF." at 246.179,113.905 h1.27
  text "LAYER NAME" at 287.454,113.905 h1.27
  text "GERBER FILE REF" at 308.206,113.829 h1.27
  text "PCB FILE" at 225.956,111.441 h1.27
  text "SpiritLevel_2E_Rev1_01" at 246.327,111.365 h1.27
  text "PcbDoc" at 277.569,111.365 h1.02
  text "Top Paste Mask" at 285.748,108.901 h1.02
  text "GTP" at 328.369,108.825 h1.27
  text "GERBER FILE" at 225.956,108.774 h1.27
  text "GTO" at 328.318,106.336 h1.27
  text "Top Overlay" at 285.748,106.31 h1.02
  text "GERBER FILE" at 225.956,106.234 h1.27
  text "Top Solder Mask" at 285.748,103.872 h1.02
  text "GTS" at 328.369,103.745 h1.27
  text "GERBER FILE" at 225.956,103.694 h1.27
  text "TOP LAYER" at 285.748,101.281 h1.02
  text "GTL" at 328.369,101.205 h1.27
  text "GERBER FILE" at 225.956,101.154 h1.27
  text "BOTTOMLAYER" at 285.748,98.801 h1.02
  text "GBL" at 328.369,98.725 h1.27
  text "GERBER FILE" at 225.956,98.614 h1.27
  text "Bottom Solder Mask" at 285.748,96.312 h1.02
  text "GBS" at 328.369,96.185 h1.27
  text "GERBER FILE" at 225.956,96.074 h1.27
  text "Bottom Overlay" at 285.748,93.721 h1.02
  text "GBO" at 328.369,93.645 h1.27
  text "GERBER FILE" at 225.956,93.534 h1.27
  text "Bottom Paste Mask" at 285.748,91.232 h1.02
  text "GBP" at 328.369,91.105 h1.27
  text "GERBER FILE" at 225.956,90.994 h1.27
  text "PCB Boundary" at 285.748,88.641 h1.02
  text "GM1" at 328.369,88.565 h1.27
  text "GERBER FILE" at 225.956,88.454 h1.27
  text "Plated Route Details" at 285.748,86.121 h1.02
  text "GM2" at 328.369,86.045 h1.27
  text "GERBER FILE" at 225.956,85.914 h1.27
  text "APERTURE LIST" at 225.956,83.411 h1.27
  text "APR" at 278.569,83.335 h1.27
  text "DRILL REPORT" at 225.956,80.871 h1.27
  text "DRR" at 278.569,80.795 h1.27
  text "EXCELLON DRILL" at 225.956,78.331 h1.27
  text "TXT" at 278.569,78.255 h1.27
  text "MATERIAL:" at 226.24,55.231 h1.52
  text "GLASS FIBRE EPOXY RESIN NEMA GRADE FR4 (MIL-S-13949H)" at 251.894,54.977 h1.27
  text "X" at 249.227,54.85 h1.52
  text "THICKNESS:" at 234.114,52.056 h1.27
  text "0.8mm" at 251.894,52.056 h1.27
  text "1.2mm" at 269.547,52.056 h1.27
  text "1.6mm" at 287.2,52.056 h1.27
  text "2.4mm" at 304.98,52.056 h1.27
  text "3.2mm" at 322.76,52.056 h1.27
  text "X" at 284.787,51.929 h1.52
  text "TOLERANCE:" at 233.987,49.008 h1.27
  text "IN A/W IPC-D-300G CLASS" at 251.64,49.008 h1.27
  text "3 LEVEL B" at 286.565,49.008 h1.27
  text "OTHER +/-" at 304.98,49.008 h1.27
  text "X" at 249.227,48.881 h1.52
  text "BOW & TWIST:" at 231.574,45.96 h1.27
  text "IN A/W IPC-D-300G CLASS" at 251.64,45.96 h1.27
  text "3 LEVEL B" at 286.565,45.96 h1.27
  text "AS SHOWN" at 305.107,45.833 h1.27
  text "X" at 249.227,45.706 h1.52
  text "COPPER THICKNESS (FINISHED)" at 233.987,42.658 h1.27
  text "OUTER:" at 238.813,40.372 h1.27
  text "18um" at 251.894,40.372 h1.27
  text "35um" at 278.945,40.372 h1.27
  text "70um" at 305.234,40.372 h1.27
  text "X" at 276.202,40.169 h1.52
  text "INNER SIGNAL:" at 230.431,37.324 h1.27
  text "18um" at 251.894,37.324 h1.27
  text "35um" at 278.945,37.324 h1.27
  text "70um" at 305.234,37.324 h1.27
  text "INNER PWR:" at 234.114,34.276 h1.27
  text "18um" at 251.894,34.276 h1.27
  text "35um" at 278.945,34.276 h1.27
  text "70um" at 305.234,34.276 h1.27
  text "STRUCTURE:" at 226.24,31.228 h1.52
  text "REFER" at 251.894,31.228 h1.27
  text "AS PER DRAWING No." at 251.767,28.053 h1.27
  text "AS SHOWN" at 305.107,28.053 h1.27
  text "X" at 302.567,27.926 h1.52
  text "DRILLING:" at 226.24,25.259 h1.52
  text "VIEWED FROM:" at 231.193,22.973 h1.27
  text "COMPONENT SIDE" at 251.894,22.973 h1.14
  text "SOLDER SIDE" at 278.691,22.973 h1.14
  text "X" at 249.227,22.719 h1.52
  text "REFERENCE:" at 233.479,19.925 h1.27
  text "AS SHOWN" at 251.767,19.798 h1.14
  text "PATTERN MASTER LIST" at 278.818,19.798 h1.14
  text "X" at 302.567,19.798 h1.52
  text "NC_DRILL FILES" at 305.107,19.798 h1.14
  text "X" at 249.227,19.671 h1.52
  text "PTH MINIMUM COPPER THICKNESS:" at 239.321,16.877 h1.27
  text "20um" at 278.945,16.877 h1.27
  text "X" at 276.278,16.75 h1.52
  text "OTHER" at 305.107,16.75 h1.27
  text "NPTH:" at 239.829,13.829 h1.27
  text "TENTED" at 251.767,13.702 h1.14
  text "X" at 276.278,13.702 h1.52
  text "PADS REMOVED" at 278.818,13.702 h1.14
  text "REMOVE PADS" at 305.107,13.702 h1.14
  text "X" at 249.227,13.575 h1.52
  text "2nd DRILL" at 251.767,10.654 h1.14
  text "BOTH" at 278.818,10.654 h1.14
  text "AS SHOWN" at 291.137,10.654 h1.14
  text "NONE" at 305.107,10.654 h1.14
  text "BOARD FINISH:" at 226.24,7.733 h1.52
  text "X" at 249.227,7.606 h1.52
  text "ETCHING" at 251.767,7.606 h1.14
  text "REFER PATTERN MASTER LIST" at 278.818,7.606 h1.14
  text "LEGEND / SCREEN PRINT:" at 246.56,4.685 h1.27
  text "NONE" at 278.818,4.558 h1.14
  text "COMPONENT" at 291.137,4.558 h1.14
  text "SOLDER" at 305.107,4.558 h1.14
  text "X" at 288.597,4.431 h1.52
  text "X" at 302.567,4.431 h1.52
  text "COLOUR:" at 236.781,1.637 h1.27
  text "WHITE" at 251.767,1.51 h1.14
  text "YELLOW" at 278.818,1.51 h1.14
  text "OTHER" at 305.107,1.51 h1.14
  text "X" at 249.227,1.383 h1.52
  text "X" at 249.227,-1.538 h1.52
  text "LIQUID PHOTOIMAGEABLE" at 251.767,-1.538 h1.14
  text "SCREEN PRINT" at 291.137,-1.538 h1.14
  text "MATTE" at 251.767,-4.586 h1.14
  text "GLOSS" at 264.467,-4.586 h1.14
  text "GREEN" at 278.818,-4.586 h1.14
  text "BLUE" at 291.137,-4.586 h1.14
  text "G/Y" at 305.107,-4.586 h1.14
  text "OTHER" at 316.537,-4.586 h1.14
  text "X" at 261.8,-4.713 h1.52
  text "SOLDER MASK COLOUR:" at 226.24,-7.507 h1.14
  text "BLACK" at 251.767,-7.634 h1.14
  text "GREEN" at 264.467,-7.634 h1.14
  text "YELLOW" at 278.818,-7.634 h1.14
  text "BLUE" at 291.137,-7.634 h1.14
  text "OTHER" at 305.107,-7.634 h1.14
  text "X" at 249.1,-7.761 h1.52
  text "TRACK FINISH:" at 226.24,-10.555 h1.52
  text "SELECTIVE SOLDER (HASL)" at 251.767,-10.682 h1.14
  text "REFLOW SOLDER" at 291.137,-10.682 h1.14
  text "X" at 249.152,-10.757 h1.52
  text "SELECTIVE GOLD" at 251.767,-13.73 h1.14
  text "um  (AREA" at 278.818,-13.73 h1.14
  text "sq. mm)" at 306.631,-13.73 h1.14
  text "REFER PATTERN MASTER LIST" at 251.767,-16.778 h1.14
  text "OTHER" at 291.137,-16.778 h1.14
  text "EDGE BOARD" at 226.24,-19.699 h1.52
  text "1.3um HARD GOLD OVER 5um     NICKEL / TIN-NICKEL" at 251.767,-19.826 h1.14
  text "CONTACTS:" at 226.24,-21.858 h1.52
  text "HARD FINISH GOLDE PLATE" at 251.767,-22.874 h1.14
  text "OTHER" at 291.137,-22.874 h1.14
  text "AS SHOWN" at 251.767,-25.922 h1.14
  text "REFER" at 291.137,-25.922 h1.14
  text "PROFILING:" at 226.24,-28.97 h1.52
  text "AS DIMENSIONED, MEASURED AND CUT FROM SPECIFIED DATUM." at 251.767,-28.97 h1.14
  text "X" at 249.227,-29.097 h1.52
  text "REFER PCB BLANK DWG No." at 251.894,-31.891 h1.27
  text "USE PROFILE / ROUTE TAPE SUPPLIED (REFER PATTERN MASTER LIST)" at 251.894,-34.939 h1.27
  text "SQUARE CUT" at 251.894,-37.987 h1.27
  text "N.C. ROUTE" at 269.674,-37.987 h1.27
  text "V. SCORE" at 287.454,-37.987 h1.27
  text "BLANK" at 305.234,-37.987 h1.27
  text "ACCEPTABILITY:" at 226.24,-40.654 h1.52
  text "MATERIALS AND WORKMANSHIP FOR ALL PRINTED WIRING BOARDS TO MEET" at 248.465,-40.781 h1.27
  text "OR EXCEED THE REQUIREMENTS OF:" at 248.465,-43.575 h1.27
  text "IPC-6011/12 AND IPC-A-600E" at 252.021,-46.242 h1.27
  text "1" at 287.581,-46.242 h1.27
  text "2" at 296.471,-46.242 h1.27
  text "X" at 293.804,-46.369 h1.52
  text "X" at 249.354,-46.496 h1.52
  text "3" at 305.361,-48.401 h1.27
  text "UL CERTIFICATION" at 252.021,-49.29 h1.27
  text "AUSTEL" at 287.581,-49.29 h1.27
  text "X" at 249.354,-49.417 h1.52
  text "ML-P-55110F GRP" at 251.513,-52.338 h1.02
  text "A" at 269.801,-52.338 h1.27
  text "B" at 278.691,-52.338 h1.27
  text "AS2546" at 287.581,-52.338 h1.27
  text "OTHER" at 305.361,-52.338 h1.27
  text "ADDITIONAL" at 226.24,-55.259 h1.52
  text "NONE" at 252.021,-55.513 h1.27
  text "SAMPLE PLAN" at 269.801,-55.513 h1.27
  text "MIL-P-55110E SERIAL Nos. PER ORDER" at 287.581,-55.513 h1.27
  text "REQUIREMENTS:" at 226.24,-57.672 h1.52
  text "NONE" at 252.021,-58.561 h1.27
  text "ML-P-55110F GRP" at 269.293,-58.561 h1.02
  text "A" at 287.581,-58.561 h1.27
  text "B" at 296.471,-58.561 h1.27
  text "IPC CLASS:" at 302.44,-58.561 h1.27
  text "1" at 317.934,-58.561 h1.27
  text "2" at 324.284,-58.561 h1.27
  text "3" at 330.634,-58.561 h1.27
  text "QUALITY RELEASE REPORT" at 269.801,-61.609 h1.27
  text "OTHER" at 310.314,-61.609 h1.27
  text "PER ORDER" at 318.823,-61.736 h1.27
  text "X" at 307.647,-61.863 h1.52
  text "NONE" at 269.801,-64.657 h1.27
  text "REQUIRED" at 287.581,-64.657 h1.27
  text "PER ORDER" at 310.441,-64.657 h1.27
  text "ELECTRICAL TEST:" at 226.24,-64.784 h1.52
  text "X" at 284.914,-64.784 h1.52
  text "NONE" at 269.801,-67.705 h1.27
  text "1 SIDE" at 287.454,-67.705 h1.14
  text "2 SIDES" at 298.63,-67.705 h1.14
  text "MIN. PITCH" at 310.314,-67.705 h1.27
  text "0.65mm" at 323.903,-67.705 h1.27
  text "SURFACE MOUNT:" at 226.24,-67.832 h1.52
  text "X" at 296.395,-67.908 h1.52
  text "NONE" at 269.801,-70.753 h1.27
  text "FOIL" at 287.581,-70.753 h1.27
  text "LEGEND" at 299.011,-70.753 h1.27
  text "REFER" at 310.314,-70.753 h1.27
  text "MANUFACTURER'S ID/LOGO:" at 226.24,-70.88 h1.52
  text "ISO9001/AS3901" at 273.611,-73.801 h1.27
  text "NONE" at 310.314,-73.801 h1.27
  text "MANUFACTURER'S ACCREDITATION:" at 226.24,-73.928 h1.52
  text "X" at 270.944,-73.928 h1.52
  text "PER ORDER" at 269.801,-76.849 h1.27
  text "REFER" at 287.581,-76.849 h1.27
  text "PACKAGING AND HANDLING:" at 226.24,-76.976 h1.52
  text "X" at 267.134,-77.103 h1.52
WS Board Travel:
  lines w0.2: 84.42,-6.5 84.42,-8.4 86.32,-6.5 87,-6.5 ; 86.4,-8.4 88.3,-6.5 ; 88.4,-8.4 90.3,-6.5 ; 90.4,-8.4 92.3,-6.5 ; 92.4,-8.4 94.3,-6.5 ; 94.4,-8.4 96.655,-6.155
  lines w0.203: 84.42,-8.4 94.7,-8.4 94.7,-10.8 98,-7.5 94.7,-4.2 94.7,-6.5 84.42,-6.5
  text "BOARD TRAVEL" at 81.56,-13.19 h1.5
Mechanical 15:
  lines w0.2: 0.3,40.7 180,40.7
Sheet Detail:
  drawing of 1882 lines, arcs and shapes, not listed
  text "1" at -27.183,163.091 h1.78
  text "2" at 21.856,163.091 h1.78
  text "3" at 71.115,163.091 h1.78
  text "4" at 120.408,163.091 h1.78
  text "5" at 169.684,163.091 h1.78
  text "6" at 218.706,163.091 h1.78
  text "7" at 268.236,163.091 h1.78
  text "8" at 317.258,163.091 h1.78
  text "A" at -49.315,129.106 h1.78
  text "A" at 339.305,129.106 h1.78
  text "B" at -49.315,58.494 h1.78
  text "B" at 339.305,58.494 h1.78
  text "C" at -49.315,-12.118 h1.78
  text "C" at 339.305,-12.118 h1.78
  text "D" at -49.315,-82.222 h1.78
  text "D" at 339.305,-82.222 h1.78
  text "ENGINEER:" at 224.37,-82.4 h1.14
  text "TITLE:" at 262.47,-82.4 h1.14
  text "PCB DESIGNER:" at 224.37,-89.893 h1.14
  text "DATE:" at 224.37,-97.64 h1.14
  text "PART NO.:" at 262.47,-97.64 h1.14
  text "REV:" at 315.81,-97.64 h1.14
  text "Altium Limited" at 191.35,-100.18 h1.78
  text ".PRINT_DATE" at 225.64,-100.688 h1.78
  text "12a Rodborough Rd" at 191.35,-102.72 h1.78
  text "Frenchs Forest" at 191.35,-105.26 h1.78
  text "FILE NAME:" at 224.37,-105.26 h1.14
  text "DWG NO:" at 262.47,-105.26 h1.14
  text "SCALE:" at 315.81,-105.26 h1.14
  text "NSW 2086" at 191.35,-107.8 h1.78
  text ".PCB_FILE_NAME_NO_PATH" at 225.64,-108.308 h1.78
  text "1" at -27.183,-113.769 h1.78
  text "2" at 21.856,-113.769 h1.78
  text "3" at 71.115,-113.769 h1.78
  text "4" at 120.408,-113.769 h1.78
  text "5" at 169.684,-113.769 h1.78
  text "6" at 218.706,-113.769 h1.78
  text "7" at 268.236,-113.769 h1.78
  text "8" at 317.258,-113.769 h1.78
Drill Drawing:
  text ".Legend" at 121,56 h1

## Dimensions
0,0 to -0.005,50.5 on Dimensions
0,-0.005 to 180,-0.005 on Dimensions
